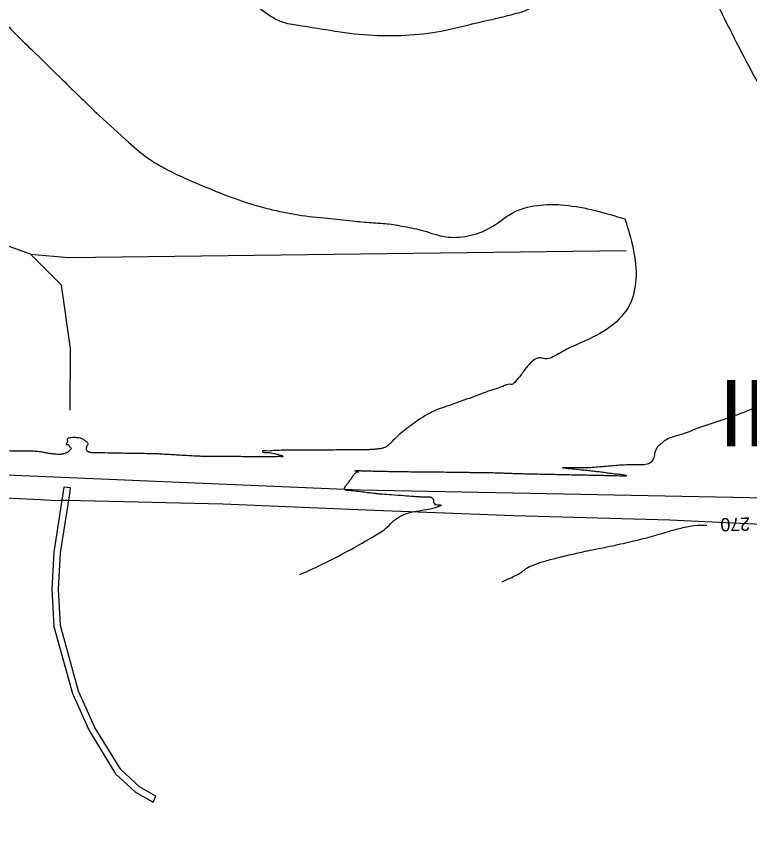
# Model space of a CAD drawing. Extents: x -478464 to -472469, y -1118040 to -1113785.
# Drawn here: x -477436.1 to -477215.2, y -1117519.9 to -1117271.8 of the extents above; entities that cross this region are included whole.
import ezdxf

# ---------------------------------------------------------------- set-up
doc = ezdxf.new("R2010")
doc.units = 0
for name, color, linetype in [('ObPÚ', 7, 'Continuous'), ('otevreni_toku', 7, 'Continuous'), ('silnice', 7, 'Continuous'), ('vodní plochy', 7, 'Continuous'), ('Vrstevnice_hlavni', 7, 'Continuous'), ('Vrstevnice_popis', 7, 'Continuous'), ('Vrstevnice_vedlejsi', 7, 'Continuous')]:
    doc.layers.add(name, color=color, linetype=linetype)

msp = doc.modelspace()

# ---------------------------------------------------------------- linework, layer by layer
at = {"layer": 'ObPÚ'}
msp.add_lwpolyline([(-477192.43, -1117425.62), (-477239.17, -1117423.45), (-477286.2, -1117422.09), (-477330.75, -1117420.42), (-477373.93, -1117418.61), (-477420.9, -1117417.49), (-477422.1, -1117417.56), (-477424.2, -1117417.6), (-477428.82, -1117417.33), (-477494.83, -1117414.18), (-477554.51, -1117411.78), (-477621.5, -1117408.68), (-477644.72, -1117408.28), (-477682.13, -1117413.46), (-477685.93, -1117414.02), (-477688.8, -1117414.36), (-477691.73, -1117414.77), (-477738.55, -1117419.44), (-477782.49, -1117430.5), (-477808.98, -1117437.26), (-477845.5, -1117449.81), (-477945.12, -1117479.46), (-478009.37, -1117499.81), (-478071.71, -1117519.91)], dxfattribs=at)
at = {"layer": 'otevreni_toku'}
for points in [[(-477419.858, -1117390.339), (-477419.782, -1117371.732), (-477422.453, -1117352.71), (-477431.845, -1117343.359), (-477451.49, -1117336.331), (-477469.302, -1117333.957), (-477495.775, -1117319.179), (-477531.288, -1117289.724), (-477552.979, -1117281.805), (-477579.09, -1117280.62), (-477623.644, -1117278.514), (-477647.889, -1117276.576), (-477670.943, -1117279.548)], [(-477431.845, -1117343.359), (-477420.24, -1117344.29), (-477252.379, -1117342.269)]]:
    msp.add_lwpolyline(points, dxfattribs=at)
at = {"layer": 'silnice'}
msp.add_lwpolyline([(-478068.596, -1117511.329), (-477917.95, -1117462.993), (-477779.219, -1117418.245), (-477732.944, -1117407.585), (-477720.808, -1117405.048), (-477704.588, -1117403.835), (-477689.402, -1117401.926), (-477652.852, -1117401.691), (-477590.784, -1117403.37), (-477332.447, -1117414.279), (-477204.956, -1117416.797), (-477142.049, -1117416.797), (-477096.756, -1117410.083), (-477036.34, -1117397.174), (-476978.492, -1117379.033), (-476883.712, -1117344.626), (-476756.221, -1117298.47), (-476633.763, -1117254.832), (-476588.47, -1117242.245), (-476550.726, -1117234.692), (-476503.755, -1117230.496), (-476424.073, -1117228.817), (-476282.324, -1117220.425)], dxfattribs=at)
at = {"layer": 'vodní plochy'}
msp.add_line((-477419.791, -1117413.702), (-477421.789, -1117413.457), dxfattribs=at)
for points in [[(-477421.789, -1117413.457), (-477424.802, -1117433.081), (-477425.36, -1117444.254), (-477424.799, -1117455.483), (-477419.215, -1117475.591), (-477414.175, -1117486.789), (-477406.182, -1117499.828), (-477400.185, -1117505.399), (-477394.906, -1117508.395), (-477394.034, -1117506.591), (-477398.995, -1117503.775), (-477404.62, -1117498.55), (-477412.403, -1117485.853), (-477417.329, -1117474.909), (-477422.813, -1117455.161), (-477423.358, -1117444.254), (-477422.81, -1117433.287), (-477419.91, -1117414.899), (-477419.791, -1117413.702)], [(-477421.789, -1117413.457), (-477421.796, -1117413.504)]]:
    msp.add_lwpolyline(points, dxfattribs=at)
at = {"layer": 'Vrstevnice_hlavni'}
for points in [[(-477153.579, -1117330.609), (-477157.863, -1117323.596), (-477159.297, -1117321.247), (-477160.024, -1117320.055), (-477160.042, -1117320.022), (-477160.06, -1117319.988), (-477160.076, -1117319.954), (-477160.092, -1117319.92), (-477162.721, -1117315.465), (-477167.963, -1117306.59), (-477175.818, -1117293.295), (-477181.552, -1117283.114), (-477185.163, -1117276.048), (-477186.654, -1117272.096), (-477188.087, -1117266.334), (-477189.463, -1117258.763), (-477190.781, -1117249.381), (-477191.646, -1117242.235), (-477192.058, -1117237.325), (-477192.016, -1117234.649), (-477191.544, -1117229.313), (-477190.643, -1117221.316), (-477189.311, -1117210.658), (-477189.553, -1117199.314), (-477191.369, -1117187.284), (-477194.759, -1117174.567), (-477196.82, -1117165.883), (-477197.552, -1117161.232), (-477196.955, -1117160.614), (-477196.962, -1117159.86), (-477197.572, -1117158.972), (-477198.786, -1117157.948), (-477199.826, -1117157.377), (-477200.692, -1117157.258), (-477201.384, -1117157.591), (-477202.438, -1117158.043), (-477203.853, -1117158.616), (-477205.629, -1117159.308), (-477208.959, -1117161.245), (-477213.844, -1117164.427), (-477220.282, -1117168.853), (-477226.049, -1117172.542), (-477231.147, -1117175.491), (-477235.573, -1117177.703), (-477239.523, -1117180.203), (-477242.996, -1117182.992), (-477248.987, -1117189.147)], [(-477289.678, -1117442), (-477287.302, -1117440.862), (-477283.774, -1117438.986), (-477282.509, -1117437.973), (-477280.339, -1117436.941), (-477277.265, -1117435.89), (-477273.286, -1117434.82), (-477268.352, -1117433.639), (-477262.464, -1117432.347), (-477255.622, -1117430.943), (-477249.39, -1117429.513), (-477243.767, -1117428.058), (-477238.754, -1117426.577), (-477234.779, -1117425.573), (-477231.842, -1117425.045), (-477228.043, -1117424.944)]]:
    msp.add_spline(points, degree=3, dxfattribs=at)
at = {"layer": 'Vrstevnice_vedlejsi'}
for points in [[(-477011.007, -1117366.824), (-477013.491, -1117363.412), (-477017.817, -1117359.784), (-477023.983, -1117355.939), (-477031.992, -1117351.878), (-477040.4, -1117349.149), (-477049.207, -1117347.752), (-477058.414, -1117347.687), (-477065.928, -1117347.539), (-477071.748, -1117347.309), (-477075.874, -1117346.996), (-477082.925, -1117343.823), (-477092.902, -1117337.789), (-477105.804, -1117328.895), (-477114.549, -1117322.878), (-477119.137, -1117319.738), (-477119.569, -1117319.477), (-477122.39, -1117317.477), (-477127.601, -1117313.741), (-477135.201, -1117308.267), (-477141.72, -1117302.085), (-477147.157, -1117295.195), (-477151.512, -1117287.597), (-477154.619, -1117282.276), (-477156.476, -1117279.232), (-477157.085, -1117278.463), (-477157.748, -1117276.952), (-477158.463, -1117274.698), (-477159.232, -1117271.701), (-477160.617, -1117267.387), (-477162.62, -1117261.756), (-477165.24, -1117254.808), (-477167.109, -1117249.303), (-477168.228, -1117245.24), (-477168.596, -1117242.62), (-477168.787, -1117237.37), (-477168.801, -1117229.491), (-477168.636, -1117218.982), (-477168.409, -1117211.034), (-477168.12, -1117205.648), (-477167.767, -1117202.824), (-477167.831, -1117199.818), (-477168.312, -1117196.63), (-477169.21, -1117193.261), (-477168.687, -1117189.852), (-477166.743, -1117186.405), (-477163.377, -1117182.919), (-477160.079, -1117178.432), (-477156.85, -1117172.943), (-477153.69, -1117166.452), (-477148.191, -1117158.76), (-477140.353, -1117149.866), (-477130.177, -1117139.771), (-477122.851, -1117132.507), (-477118.377, -1117128.073), (-477116.755, -1117126.471), (-477114.695, -1117124.861), (-477112.2, -1117123.245), (-477109.268, -1117121.623), (-477108.831, -1117118.293), (-477110.89, -1117113.256), (-477115.445, -1117106.513), (-477120.426, -1117101.765), (-477125.832, -1117099.012), (-477131.665, -1117098.254), (-477138.053, -1117097.27), (-477144.998, -1117096.058), (-477152.499, -1117094.62), (-477159.769, -1117094.465), (-477166.808, -1117095.596), (-477173.616, -1117098.01), (-477180.33, -1117100.679), (-477186.95, -1117103.602), (-477193.475, -1117106.78), (-477198.483, -1117109.356), (-477201.974, -1117111.331), (-477203.948, -1117112.704), (-477206.839, -1117114.278), (-477210.647, -1117116.052), (-477215.372, -1117118.026), (-477220.015, -1117120.06), (-477224.576, -1117122.155), (-477229.056, -1117124.31), (-477232.76, -1117126.026), (-477235.69, -1117127.304), (-477237.845, -1117128.144), (-477243.607, -1117132.15), (-477252.977, -1117139.322), (-477265.953, -1117149.661), (-477274.723, -1117156.675), (-477279.287, -1117160.365), (-477279.643, -1117160.729), (-477283.158, -1117162.018), (-477289.832, -1117164.231), (-477299.663, -1117167.368), (-477307.385, -1117170.123), (-477312.997, -1117172.497)], [(-477242.816, -1117401.206), (-477242.33, -1117400.788), (-477241.801, -1117400.341), (-477241.229, -1117399.866), (-477240.615, -1117399.363), (-477236.987, -1117397.929), (-477230.346, -1117395.561), (-477220.692, -1117392.262), (-477213.029, -1117389.419), (-477207.358, -1117387.033), (-477203.679, -1117385.104), (-477198.765, -1117383.705), (-477192.616, -1117382.835), (-477185.231, -1117382.494), (-477180.359, -1117379.804), (-477178.001, -1117374.763), (-477178.155, -1117367.373), (-477179.951, -1117358.721), (-477183.387, -1117348.807), (-477188.465, -1117337.631), (-477192.245, -1117329.464), (-477194.727, -1117324.304), (-477195.91, -1117322.151), (-477197.022, -1117320.01), (-477198.062, -1117317.881), (-477199.031, -1117315.762), (-477201.828, -1117310.612), (-477206.453, -1117302.429), (-477212.906, -1117291.215), (-477218.991, -1117279.805), (-477224.706, -1117268.2), (-477230.053, -1117256.4), (-477233.791, -1117248.023), (-477235.922, -1117243.067), (-477236.445, -1117241.534), (-477237.131, -1117240.196), (-477237.979, -1117239.054), (-477238.989, -1117238.108), (-477240.099, -1117237.792), (-477241.308, -1117238.108), (-477242.616, -1117239.054), (-477247.496, -1117242.927), (-477255.949, -1117249.728), (-477267.975, -1117259.456), (-477276.908, -1117266.227), (-477282.75, -1117270.039), (-477285.501, -1117270.894), (-477290.862, -1117272.253), (-477298.834, -1117274.115), (-477309.417, -1117276.481), (-477320.28, -1117277.55), (-477331.422, -1117277.32), (-477342.843, -1117275.793), (-477351.095, -1117274.483), (-477356.177, -1117273.39), (-477358.088, -1117272.515), (-477363.807, -1117268.569), (-477373.333, -1117261.552), (-477386.667, -1117251.464), (-477395.708, -1117244.586), (-477400.459, -1117240.917), (-477400.917, -1117240.459), (-477405.515, -1117237.519), (-477414.252, -1117232.098), (-477427.127, -1117224.195), (-477436.796, -1117218.202), (-477443.259, -1117214.119), (-477446.516, -1117211.946), (-477449.727, -1117209.411), (-477452.893, -1117206.515), (-477456.014, -1117203.258), (-477459.048, -1117199.241), (-477461.994, -1117194.464), (-477464.853, -1117188.928), (-477466.734, -1117184.683), (-477467.638, -1117181.729), (-477467.564, -1117180.066), (-477467.628, -1117178.904), (-477467.829, -1117178.243), (-477468.169, -1117178.084), (-477468.447, -1117177.976), (-477468.662, -1117177.92), (-477468.815, -1117177.914), (-477468.774, -1117177.844), (-477468.538, -1117177.708), (-477468.108, -1117177.506), (-477467.675, -1117177.3), (-477467.24, -1117177.089), (-477466.803, -1117176.874), (-477466.105, -1117176.551), (-477465.147, -1117176.119), (-477463.929, -1117175.579), (-477461.972, -1117174.773), (-477459.277, -1117173.703), (-477455.843, -1117172.368), (-477453.286, -1117171.289), (-477451.604, -1117170.465)], [(-477490.07, -1117220.505), (-477485.035, -1117225.923), (-477481.208, -1117230.027), (-477478.588, -1117232.815), (-477477.176, -1117234.289), (-477475.528, -1117235.743), (-477473.645, -1117237.177), (-477471.527, -1117238.591), (-477468.39, -1117241.076), (-477464.234, -1117244.633), (-477459.06, -1117249.262), (-477454.067, -1117254.508), (-477449.257, -1117260.373), (-477444.629, -1117266.854), (-477440.803, -1117271.916), (-477437.779, -1117275.557), (-477435.556, -1117277.779), (-477430.37, -1117282.857), (-477422.222, -1117290.793), (-477411.111, -1117301.586), (-477402.278, -1117309.628), (-477395.723, -1117314.919), (-477391.446, -1117317.46), (-477385.576, -1117320.321), (-477378.112, -1117323.502), (-477369.056, -1117327.004), (-477360.076, -1117329.674), (-477351.172, -1117331.509), (-477342.343, -1117332.512), (-477334.956, -1117333.29), (-477329.01, -1117333.843), (-477324.505, -1117334.172), (-477319.29, -1117334.992), (-477313.364, -1117336.303), (-477306.728, -1117338.105), (-477300.072, -1117337.815), (-477293.395, -1117335.431), (-477286.697, -1117330.955), (-477279.201, -1117328.664), (-477270.907, -1117328.559), (-477252.72, -1117332.72)], [(-477252.72, -1117332.72), (-477249.442, -1117350.907), (-477251.399, -1117358.647), (-477256.954, -1117365.034), (-477266.106, -1117370.068), (-477272.734, -1117373.328), (-477276.839, -1117374.815), (-477278.419, -1117374.529), (-477280.163, -1117375.266), (-477282.069, -1117377.024), (-477284.137, -1117379.804), (-477285.708, -1117381.646), (-477286.782, -1117382.55), (-477287.358, -1117382.516), (-477289.514, -1117383.138), (-477293.25, -1117384.416), (-477298.565, -1117386.349), (-477302.966, -1117387.928), (-477306.451, -1117389.154), (-477309.021, -1117390.026), (-477311.669, -1117391.276), (-477314.394, -1117392.903), (-477317.197, -1117394.908), (-477319.486, -1117396.657), (-477321.26, -1117398.15), (-477322.52, -1117399.387), (-477323.516, -1117400.341), (-477324.249, -1117401.012), (-477324.718, -1117401.399), (-477325.454, -1117401.703), (-477326.457, -1117401.923), (-477327.727, -1117402.06), (-477328.933, -1117402.16), (-477330.077, -1117402.221), (-477331.158, -1117402.245), (-477332.75, -1117402.264), (-477334.854, -1117402.279), (-477337.471, -1117402.29), (-477340.599, -1117402.31), (-477344.24, -1117402.337), (-477348.392, -1117402.371), (-477351.464, -1117402.395), (-477353.456, -1117402.406), (-477354.368, -1117402.406), (-477355.068, -1117402.403), (-477355.558, -1117402.399), (-477355.837, -1117402.392), (-477356.81, -1117402.42), (-477358.476, -1117402.483), (-477360.836, -1117402.58), (-477361.948, -1117402.705), (-477361.81, -1117402.861), (-477360.423, -1117403.045), (-477359.31, -1117403.205), (-477358.471, -1117403.34), (-477357.906, -1117403.451), (-477357.287, -1117403.611), (-477356.616, -1117403.818), (-477355.892, -1117404.072), (-477355.822, -1117404.241), (-477356.404, -1117404.324), (-477357.64, -1117404.32), (-477359.149, -1117404.327), (-477360.932, -1117404.343), (-477362.988, -1117404.369), (-477364.621, -1117404.377), (-477365.832, -1117404.368), (-477366.619, -1117404.34), (-477368.472, -1117404.314), (-477371.39, -1117404.29), (-477375.373, -1117404.266), (-477378.256, -1117404.244), (-477380.04, -1117404.225), (-477380.724, -1117404.208), (-477382.599, -1117404.115), (-477385.666, -1117403.945), (-477389.925, -1117403.698), (-477392.944, -1117403.533), (-477394.725, -1117403.45), (-477395.267, -1117403.448), (-477395.831, -1117403.442), (-477396.419, -1117403.433), (-477397.029, -1117403.42), (-477399.108, -1117403.384), (-477402.657, -1117403.323), (-477407.675, -1117403.239), (-477411.11, -1117403.18), (-477412.96, -1117403.147), (-477413.228, -1117403.138), (-477413.484, -1117403.113), (-477413.73, -1117403.071), (-477413.965, -1117403.013), (-477414.17, -1117402.951), (-477414.344, -1117402.886), (-477414.489, -1117402.817), (-477414.611, -1117402.734), (-477414.713, -1117402.635)], [(-477414.713, -1117402.635), (-477414.793, -1117402.52), (-477414.862, -1117402.382), (-477414.919, -1117402.22), (-477414.964, -1117402.035), (-477414.971, -1117401.827), (-477414.94, -1117401.597), (-477414.871, -1117401.344), (-477414.776, -1117401.092), (-477414.656, -1117400.84), (-477414.509, -1117400.588), (-477414.5, -1117400.343), (-477414.626, -1117400.104), (-477414.889, -1117399.873), (-477415.271, -1117399.599), (-477415.77, -1117399.284), (-477416.387, -1117398.926), (-477417.221, -1117398.692), (-477418.272, -1117398.582), (-477419.539, -1117398.595), (-477420.369, -1117398.755), (-477420.761, -1117399.064), (-477420.717, -1117399.521), (-477420.751, -1117399.907), (-477420.865, -1117400.222), (-477421.058, -1117400.465), (-477421.095, -1117400.623), (-477420.976, -1117400.696), (-477420.702, -1117400.684), (-477420.48, -1117400.735), (-477420.311, -1117400.849), (-477420.194, -1117401.026), (-477420.072, -1117401.2), (-477419.944, -1117401.372), (-477419.811, -1117401.542), (-477419.721, -1117401.681), (-477419.672, -1117401.789), (-477419.665, -1117401.866), (-477419.669, -1117401.942), (-477419.684, -1117402.017), (-477419.709, -1117402.092), (-477419.743, -1117402.15), (-477419.788, -1117402.192), (-477419.844, -1117402.219), (-477419.949, -1117402.313), (-477420.105, -1117402.475), (-477420.31, -1117402.706), (-477420.47, -1117402.874), (-477420.583, -1117402.98), (-477420.65, -1117403.024), (-477420.838, -1117403.102), (-477421.149, -1117403.215), (-477421.582, -1117403.362), (-477421.986, -1117403.481), (-477422.363, -1117403.572), (-477422.711, -1117403.635), (-477423.284, -1117403.642), (-477424.082, -1117403.593), (-477425.105, -1117403.49), (-477426.142, -1117403.353), (-477427.192, -1117403.183), (-477428.258, -1117402.98), (-477429.215, -1117402.833), (-477430.065, -1117402.74), (-477430.807, -1117402.703), (-477432.264, -1117402.67), (-477434.436, -1117402.641), (-477437.323, -1117402.616), (-477439.628, -1117402.593), (-477441.351, -1117402.574), (-477442.491, -1117402.558), (-477443.834, -1117402.533), (-477445.382, -1117402.5), (-477447.133, -1117402.459), (-477448.678, -1117402.425), (-477450.018, -1117402.398), (-477451.151, -1117402.378), (-477452.057, -1117402.337), (-477452.737, -1117402.276), (-477453.19, -1117402.193), (-477453.748, -1117402.072), (-477454.411, -1117401.913), (-477455.18, -1117401.716), (-477455.749, -1117401.582), (-477456.119, -1117401.512), (-477456.289, -1117401.504), (-477456.686, -1117401.505), (-477457.31, -1117401.514), (-477458.161, -1117401.531), (-477458.996, -1117401.585), (-477459.816, -1117401.675), (-477460.62, -1117401.803), (-477461.416, -1117401.885), (-477462.205, -1117401.921), (-477462.986, -1117401.912), (-477464.188, -1117401.874), (-477465.81, -1117401.807)], [(-477327.901, -1117415.45), (-477328.37, -1117415.407), (-477329.337, -1117415.294), (-477330.802, -1117415.109), (-477332.763, -1117414.853), (-477334.415, -1117414.652), (-477335.757, -1117414.508), (-477336.789, -1117414.419), (-477337.25, -1117414.076), (-477337.139, -1117413.48), (-477336.456, -1117412.63), (-477335.796, -1117411.752), (-477335.159, -1117410.844), (-477334.546, -1117409.906), (-477333.982, -1117409.264), (-477333.469, -1117408.918), (-477333.006, -1117408.867), (-477332.952, -1117408.792), (-477333.306, -1117408.693), (-477334.069, -1117408.572), (-477333.693, -1117408.518), (-477332.176, -1117408.533), (-477329.52, -1117408.616), (-477327.678, -1117408.673), (-477326.65, -1117408.701), (-477326.435, -1117408.702), (-477325.121, -1117408.721), (-477322.709, -1117408.756), (-477319.198, -1117408.809), (-477316.698, -1117408.842), (-477315.21, -1117408.856), (-477314.734, -1117408.85), (-477314.188, -1117408.85), (-477313.571, -1117408.855), (-477312.885, -1117408.866), (-477311.356, -1117408.884), (-477308.985, -1117408.911), (-477305.772, -1117408.946), (-477303.301, -1117408.975), (-477301.572, -1117408.998), (-477300.585, -1117409.016), (-477299.025, -1117409.038), (-477296.891, -1117409.065), (-477294.184, -1117409.097), (-477291.924, -1117409.139), (-477290.111, -1117409.192), (-477288.744, -1117409.255), (-477287.246, -1117409.315), (-477285.617, -1117409.37), (-477283.855, -1117409.421), (-477281.83, -1117409.471), (-477279.54, -1117409.519), (-477276.987, -1117409.566), (-477274.786, -1117409.61), (-477272.936, -1117409.65), (-477271.438, -1117409.687), (-477269.537, -1117409.727), (-477267.234, -1117409.771), (-477264.529, -1117409.817), (-477262.433, -1117409.857), (-477260.946, -1117409.889), (-477260.07, -1117409.915), (-477258.516, -1117409.953), (-477256.285, -1117410.005), (-477253.377, -1117410.07), (-477252.223, -1117410.023), (-477252.824, -1117409.865), (-477255.18, -1117409.597), (-477257.247, -1117409.351), (-477259.025, -1117409.129), (-477260.513, -1117408.931), (-477261.893, -1117408.76), (-477263.165, -1117408.617), (-477264.329, -1117408.502), (-477265.966, -1117408.334), (-477268.076, -1117408.115), (-477270.659, -1117407.844), (-477271.519, -1117407.66), (-477270.654, -1117407.563), (-477268.065, -1117407.553), (-477266.158, -1117407.555), (-477264.933, -1117407.569), (-477264.39, -1117407.597), (-477263.358, -1117407.557), (-477261.836, -1117407.45), (-477259.824, -1117407.277), (-477257.833, -1117407.109), (-477255.862, -1117406.946), (-477253.912, -1117406.788), (-477251.781, -1117406.689), (-477249.468, -1117406.647), (-477246.974, -1117406.663), (-477245.181, -1117406.113), (-477244.087, -1117404.995), (-477243.695, -1117403.31), (-477243.271, -1117402.047), (-477242.816, -1117401.206)], [(-477350.646, -1117439.791), (-477348.222, -1117438.741), (-477342.041, -1117435.763), (-477334.145, -1117431.602), (-477328.229, -1117428.175), (-477324.292, -1117425.483), (-477322.335, -1117423.525), (-477319.944, -1117422.038), (-477317.119, -1117421.021), (-477313.86, -1117420.475), (-477311.406, -1117420.004), (-477309.756, -1117419.607), (-477308.91, -1117419.286), (-477308.356, -1117419.07), (-477308.093, -1117418.96), (-477308.122, -1117418.955), (-477308.383, -1117418.936), (-477308.877, -1117418.903), (-477309.603, -1117418.855), (-477310.03, -1117418.794), (-477310.157, -1117418.722), (-477309.984, -1117418.638), (-477309.934, -1117418.546), (-477310.008, -1117418.448), (-477310.205, -1117418.342), (-477310.325, -1117418.174), (-477310.37, -1117417.944), (-477310.338, -1117417.652), (-477310.335, -1117417.428), (-477310.361, -1117417.271), (-477310.416, -1117417.183), (-477310.5, -1117417.084), (-477310.612, -1117416.976), (-477310.753, -1117416.857), (-477310.885, -1117416.749), (-477311.008, -1117416.654), (-477311.121, -1117416.57), (-477311.439, -1117416.518), (-477311.961, -1117416.496), (-477312.686, -1117416.504), (-477313.378, -1117416.501), (-477314.036, -1117416.486), (-477314.661, -1117416.458), (-477316.388, -1117416.339), (-477319.219, -1117416.129), (-477323.154, -1117415.827), (-477325.791, -1117415.625), (-477327.131, -1117415.52), (-477327.173, -1117415.514), (-477327.226, -1117415.508), (-477327.287, -1117415.503), (-477327.359, -1117415.498), (-477327.563, -1117415.48), (-477327.901, -1117415.45)]]:
    msp.add_spline(points, degree=3, dxfattribs=at)

# ---------------------------------------------------------------- texts
at = {"layer": 'silnice'}
msp.add_text('III/4807', height=20, dxfattribs=at).set_placement((-477224.453, -1117401.229))
at = {"layer": 'Vrstevnice_popis'}
msp.add_text(' 270 ', height=4, rotation=181.52987, dxfattribs=at).set_placement((-477213.619, -1117422.557))

doc.saveas('drawing.dxf')
